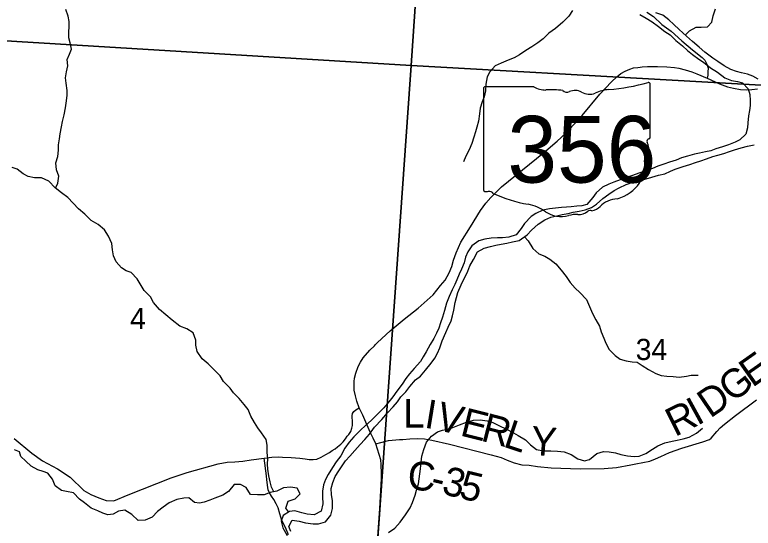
# Model space of a CAD drawing. Extents: x -8.2 to 34, y 0 to 22.
# Drawn here: x 3.755 to 5.214, y 18.871 to 19.885 of the extents above; entities that cross this region are included whole.
import ezdxf

# ---------------------------------------------------------------- set-up
doc = ezdxf.new("R2010")
doc.units = 0
for name, color, linetype in [('GM_X_Corporation', 7, 'Continuous'), ('GM_X_County_Road', 7, 'Continuous'), ('GM_X_County_Road_Text', 7, 'Continuous'), ('GM_X_Major_River', 7, 'Continuous'), ('GM_X_Minor_River', 7, 'Continuous'), ('GM_X_Section_Text', 7, 'Continuous'), ('GM_X_State_Location', 7, 'Continuous'), ('GM_X_State_Route', 7, 'Continuous'), ('GM_X_State_Shield', 7, 'Continuous'), ('GM_X_Township_Road', 7, 'Continuous')]:
    doc.layers.add(name, color=color, linetype=linetype)

msp = doc.modelspace()

# ---------------------------------------------------------------- linework, layer by layer
at = {"layer": 'GM_X_Corporation'}
for points in [[(4.607, 20.8038), (4.5379, 19.7849), (3.5308, 19.8461), (3.6063, 20.8752)], [(5.6414, 20.7386), (5.5693, 19.7272), (4.5379, 19.7849), (4.607, 20.8038)], [(3.5308, 19.8461), (4.5379, 19.7849), (4.465, 18.749), (3.459, 18.8121), (3.474, 19.0276), (3.5026, 19.4408)], [(4.5379, 19.7849), (5.5693, 19.7272), (5.5363, 19.3151), (5.5032, 18.9017), (5.4857, 18.6849), (4.465, 18.749)]]:
    msp.add_lwpolyline(points, close=True, dxfattribs=at)
at = {"layer": 'GM_X_County_Road'}
msp.add_lwpolyline([(4.4679, 19.0374), (4.4779, 19.0404), (4.4929, 19.0441), (4.5151, 19.0461), (4.5212, 19.0462), (4.5351, 19.0475), (4.5503, 19.0479), (4.5639, 19.0473), (4.5787, 19.0448), (4.6137, 19.0366), (4.6961, 19.0158), (4.7154, 19.0105), (4.7277, 19.0054), (4.7413, 18.9998), (4.7567, 18.9961), (4.7707, 18.9952), (4.7878, 18.9927), (4.8147, 18.9898), (4.8716, 18.9879), (4.9192, 18.9886), (4.9437, 18.9905), (4.9718, 18.996), (4.9816, 18.998), (5.0094, 19.0035), (5.0206, 19.0079), (5.0312, 19.0126), (5.0486, 19.0207), (5.073, 19.0288), (5.1145, 19.0416), (5.1272, 19.0459), (5.1305, 19.0487), (5.1419, 19.0618), (5.1482, 19.0694), (5.1568, 19.0762), (5.1785, 19.0933), (5.2199, 19.1245)], dxfattribs=at)
at = {"layer": 'GM_X_Major_River'}
for points in [[(5.1435, 19.7929), (5.1337, 19.7998), (5.1181, 19.8116), (5.1071, 19.8211), (5.0935, 19.8325), (5.0817, 19.8428), (5.0673, 19.8561), (5.0567, 19.8659), (5.0472, 19.8754), (5.0351, 19.8846), (5.021, 19.8895)], [(4.9895, 19.8861), (5.0024, 19.8789), (5.0142, 19.8717), (5.0267, 19.8625), (5.0388, 19.8523), (5.0495, 19.8454), (5.0608, 19.8348), (5.0737, 19.8242), (5.084, 19.8146), (5.0938, 19.807), (5.1064, 19.7975), (5.1158, 19.7915), (5.1295, 19.7804), (5.1431, 19.7717), (5.1576, 19.761), (5.1705, 19.7557), (5.1826, 19.7538), (5.1925, 19.7507), (5.2035, 19.7393), (5.2072, 19.728), (5.208, 19.7162), (5.208, 19.7059), (5.2065, 19.6964), (5.2046, 19.6854), (5.2034, 19.6721), (5.2027, 19.6619), (5.1989, 19.6497), (5.1875, 19.6384), (5.178, 19.6338), (5.1651, 19.6285), (5.1529, 19.6243), (5.14, 19.6202), (5.1298, 19.6168), (5.1192, 19.6145), (5.1078, 19.6122), (5.0975, 19.6096), (5.0839, 19.6062), (5.0721, 19.6028), (5.0615, 19.5978), (5.0486, 19.5941), (5.0368, 19.5903), (5.0254, 19.5861), (5.0144, 19.5819), (5.0027, 19.5774), (4.9875, 19.5721), (4.975, 19.5675), (4.9624, 19.5638), (4.9507, 19.5592), (4.9381, 19.5547), (4.9287, 19.5509), (4.9158, 19.5444), (4.9036, 19.5338), (4.8968, 19.524), (4.885, 19.5107), (4.8751, 19.5076), (4.8649, 19.5069), (4.8543, 19.5058), (4.8448, 19.505), (4.8349, 19.5043), (4.8228, 19.5031), (4.811, 19.5016), (4.7977, 19.4994), (4.7845, 19.4929), (4.775, 19.4869)], [(5.2232, 19.7583), (5.213, 19.764), (5.2027, 19.7678), (5.1906, 19.7709), (5.1807, 19.7732), (5.1697, 19.7774), (5.1561, 19.7842), (5.1435, 19.7929)], [(4.4082, 19.0038), (4.4169, 19.0133), (4.4268, 19.0243), (4.4374, 19.0364), (4.4462, 19.0463), (4.4553, 19.0569), (4.4651, 19.0702), (4.48, 19.0858), (4.491, 19.0987), (4.502, 19.1108), (4.5111, 19.1207), (4.5175, 19.1305), (4.527, 19.1404), (4.5354, 19.151), (4.5464, 19.1639), (4.5563, 19.1715), (4.5661, 19.1829), (4.5771, 19.1969), (4.5847, 19.2068), (4.5897, 19.2167), (4.5942, 19.2269), (4.5992, 19.241), (4.6064, 19.2577), (4.6109, 19.2679), (4.617, 19.2808), (4.6197, 19.2907), (4.6223, 19.3017), (4.625, 19.3165), (4.6277, 19.3268), (4.6303, 19.3366), (4.6364, 19.3518), (4.6497, 19.3784), (4.6539, 19.389), (4.6607, 19.4019), (4.6687, 19.4167), (4.6824, 19.4243), (4.6949, 19.4277), (4.7051, 19.4303), (4.7157, 19.4322), (4.7271, 19.4341), (4.7381, 19.4364), (4.751, 19.439), (4.767, 19.4504), (4.7757, 19.4599), (4.789, 19.4717), (4.8019, 19.48), (4.814, 19.4853), (4.8258, 19.4883), (4.8361, 19.4906), (4.8478, 19.4929), (4.8581, 19.4951), (4.8698, 19.497), (4.8816, 19.5), (4.8945, 19.5046), (4.904, 19.511), (4.9169, 19.522), (4.9287, 19.5311), (4.9393, 19.5383), (4.9491, 19.5436), (4.9624, 19.5497), (4.9761, 19.5543), (4.9882, 19.5577), (5.0023, 19.5614), (5.0137, 19.5645), (5.0266, 19.5683), (5.0391, 19.5713), (5.0501, 19.5762), (5.0596, 19.58), (5.0751, 19.5857), (5.0884, 19.5895), (5.0994, 19.5933), (5.1104, 19.5967), (5.1214, 19.6004), (5.134, 19.605), (5.1438, 19.608), (5.1556, 19.6114), (5.167, 19.6152), (5.1768, 19.6186), (5.1897, 19.6224), (5.2023, 19.6258), (5.2159, 19.6285)], [(4.775, 19.4869), (4.7621, 19.4732), (4.7552, 19.4633), (4.745, 19.4508), (4.7309, 19.4459), (4.718, 19.4448), (4.7085, 19.4448), (4.6956, 19.444), (4.6835, 19.4418), (4.6714, 19.4384), (4.6577, 19.4285), (4.6497, 19.4167), (4.6455, 19.4061), (4.6425, 19.3955), (4.6372, 19.3826), (4.633, 19.3727), (4.6284, 19.3617), (4.6239, 19.3522), (4.6189, 19.3416), (4.6129, 19.3287), (4.6079, 19.3158), (4.6038, 19.3013), (4.5996, 19.2877), (4.5958, 19.2767), (4.5924, 19.266), (4.5882, 19.2562), (4.5825, 19.2459), (4.5753, 19.2338), (4.5677, 19.2193), (4.5616, 19.2095), (4.5563, 19.2), (4.5441, 19.1863), (4.5346, 19.1761), (4.5274, 19.1666), (4.5202, 19.1556), (4.5096, 19.1416), (4.5016, 19.1302), (4.494, 19.1207), (4.4838, 19.1089), (4.4709, 19.0953), (4.4587, 19.0839), (4.4477, 19.074), (4.4378, 19.0645), (4.4245, 19.0516), (4.4151, 19.0406), (4.4071, 19.0289), (4.3991, 19.0141), (4.3896, 19.0019), (4.3824, 18.9905), (4.3737, 18.9769), (4.3683, 18.967), (4.3645, 18.9568), (4.3626, 18.9442), (4.3626, 18.9325), (4.363, 18.9188), (4.36, 18.9047), (4.3463, 18.8972), (4.3323, 18.8983), (4.322, 18.901), (4.308, 18.9052), (4.2977, 18.9037), (4.2848, 18.8961), (4.2807, 18.8847), (4.2844, 18.8714), (4.2928, 18.8562)], [(4.3004, 18.8645), (4.2962, 18.8744), (4.303, 18.8866), (4.3163, 18.8846), (4.3288, 18.8812), (4.344, 18.8793), (4.355, 18.8793), (4.3683, 18.8835), (4.3789, 18.8967), (4.3824, 18.91), (4.3824, 18.9248), (4.3805, 18.9374), (4.3801, 18.9495), (4.3831, 18.9613), (4.3877, 18.9727), (4.3949, 18.9844), (4.4014, 18.9943), (4.4082, 19.0038)]]:
    msp.add_lwpolyline(points, dxfattribs=at)
at = {"layer": 'GM_X_Minor_River'}
for points in [[(3.8352, 19.5427), (3.8395, 19.5527), (3.8414, 19.5663), (3.8372, 19.5792), (3.836, 19.5925), (3.8394, 19.6054), (3.8409, 19.6176), (3.8413, 19.6282), (3.8428, 19.6403), (3.8443, 19.6502), (3.8466, 19.6642), (3.8488, 19.6745), (3.8522, 19.6877), (3.8545, 19.7014), (3.8567, 19.7154), (3.8579, 19.7264), (3.8578, 19.7359), (3.8563, 19.7503), (3.8548, 19.7606), (3.8567, 19.7727), (3.8593, 19.7845), (3.8578, 19.797), (3.8627, 19.8072), (3.8668, 19.8171), (3.8638, 19.83), (3.8615, 19.8399), (3.8615, 19.8516), (3.8619, 19.8615), (3.8619, 19.8721), (3.8599, 19.8827), (3.8554, 19.896)], [(4.8566, 19.8935), (4.8494, 19.8829), (4.8373, 19.8707), (4.8229, 19.8582), (4.81, 19.8487), (4.7987, 19.8381), (4.7881, 19.8297), (4.7764, 19.8218), (4.7646, 19.8146), (4.7518, 19.8062), (4.7416, 19.8001), (4.7298, 19.7959), (4.7158, 19.7895), (4.7037, 19.7842), (4.6931, 19.7724), (4.6878, 19.7625), (4.6852, 19.7481), (4.6848, 19.7352), (4.6818, 19.7231), (4.6784, 19.7136), (4.6743, 19.7011), (4.6732, 19.6897), (4.6709, 19.6749), (4.6679, 19.6635), (4.6649, 19.654), (4.6618, 19.6438), (4.6577, 19.6309), (4.6524, 19.6188), (4.646, 19.6059), (4.6415, 19.5949)], [(5.079, 19.8452), (5.0876, 19.8534), (5.1008, 19.861), (5.1107, 19.8606), (5.1232, 19.8614), (5.1319, 19.8709), (5.1345, 19.883), (5.1394, 19.8974)], [(4.2668, 18.9428), (4.2616, 18.9517), (4.2594, 18.9623), (4.2567, 18.9744), (4.2548, 18.9873), (4.254, 18.9976), (4.2548, 19.0086), (4.2536, 19.0207), (4.2532, 19.0347), (4.2513, 19.0461), (4.2418, 19.0594), (4.235, 19.0689), (4.2282, 19.0795), (4.2213, 19.0924), (4.216, 19.1053), (4.2081, 19.1151), (4.1982, 19.1269), (4.1865, 19.1383), (4.18, 19.1477), (4.1671, 19.161), (4.1607, 19.1716), (4.1489, 19.1838), (4.1364, 19.1955), (4.1247, 19.2054), (4.1152, 19.2198), (4.1121, 19.2323), (4.1125, 19.2425), (4.1068, 19.2566), (4.0943, 19.2645), (4.081, 19.2698), (4.0655, 19.2816), (4.0534, 19.2922), (4.0405, 19.3032), (4.0287, 19.3168), (4.023, 19.3278), (4.0105, 19.3407), (4.0045, 19.3506), (3.9965, 19.3635), (3.9844, 19.376), (3.9749, 19.3794), (3.9654, 19.3855), (3.9548, 19.3972), (3.9499, 19.409), (3.9476, 19.4211), (3.9464, 19.4336), (3.9396, 19.448), (3.9316, 19.4602), (3.9191, 19.4712), (3.9055, 19.4791), (3.8933, 19.4913), (3.8808, 19.5019), (3.8596, 19.5246), (3.8471, 19.5333), (3.8346, 19.5432), (3.8221, 19.5565), (3.8077, 19.5629), (3.7937, 19.5633), (3.7812, 19.5655), (3.7713, 19.5709), (3.7592, 19.58), (3.7493, 19.5834)], [(4.7619, 19.4468), (4.7692, 19.4386), (4.7783, 19.4238), (4.7901, 19.4129), (4.8022, 19.4083), (4.8117, 19.4022), (4.8234, 19.3935), (4.8344, 19.381), (4.8439, 19.3681), (4.8523, 19.356), (4.8617, 19.3454), (4.8712, 19.3363), (4.8841, 19.3226), (4.8902, 19.3086), (4.8959, 19.2949), (4.9027, 19.2828), (4.9099, 19.2699), (4.9133, 19.2589), (4.9187, 19.246), (4.9228, 19.2365), (4.9293, 19.224), (4.9407, 19.2123), (4.9509, 19.2051), (4.9626, 19.2013), (4.9747, 19.1998), (4.9846, 19.1986), (4.9944, 19.1926), (5.007, 19.1842), (5.021, 19.1766), (5.0316, 19.1725), (5.0429, 19.171), (5.0554, 19.1706), (5.0676, 19.1691), (5.0816, 19.1714), (5.0914, 19.1729), (5.105, 19.1729)], [(4.4931, 18.8623), (4.5056, 18.871), (4.5158, 18.8828), (4.5264, 18.8972), (4.5358, 18.9112), (4.5407, 18.9219), (4.546, 18.9359), (4.5487, 18.9461), (4.5524, 18.9583), (4.5536, 18.9681), (4.5547, 18.9784), (4.5566, 18.9879), (4.5577, 19.0012), (4.5592, 19.0129), (4.5626, 19.0262), (4.5683, 19.041), (4.5781, 19.0524), (4.5902, 19.0615), (4.6, 19.0645), (4.6103, 19.0664), (4.6205, 19.0695), (4.6333, 19.0748), (4.647, 19.0805), (4.661, 19.0843), (4.6742, 19.085), (4.6882, 19.0832), (4.6992, 19.0797), (4.7121, 19.0729), (4.7246, 19.0669), (4.7401, 19.0593), (4.7496, 19.054), (4.7636, 19.0453), (4.7735, 19.0358), (4.7852, 19.0263), (4.7996, 19.0237), (4.814, 19.0237), (4.8273, 19.0233), (4.8405, 19.0214), (4.8538, 19.0165), (4.8674, 19.0081), (4.8803, 19.0036), (4.8905, 19.0063), (4.9045, 19.0184), (4.9182, 19.0226), (4.9291, 19.0218), (4.9413, 19.0196), (4.9522, 19.0165), (4.9655, 19.0139), (4.9784, 19.0124), (4.9886, 19.0131), (5.0015, 19.0184), (5.0147, 19.0272), (5.0253, 19.0336), (5.0393, 19.0397), (5.0533, 19.0427), (5.0632, 19.045), (5.0756, 19.0473), (5.0874, 19.0507), (5.1014, 19.0587), (5.1135, 19.0682)], [(4.2963, 18.9028), (4.2905, 18.9107), (4.295, 18.924), (4.3086, 18.9289), (4.3188, 18.9388), (4.3124, 18.9502), (4.2991, 18.9521), (4.2855, 18.9506), (4.2723, 18.9441), (4.2594, 18.9411), (4.2476, 18.9365), (4.234, 18.9365), (4.2204, 18.9376), (4.2117, 18.9513), (4.2007, 18.957), (4.1878, 18.9573), (4.1772, 18.9433), (4.1655, 18.9361), (4.15, 18.93), (4.1397, 18.9262), (4.1291, 18.9224), (4.1193, 18.9205), (4.1095, 18.9216), (4.0988, 18.9311), (4.0886, 18.9303), (4.0746, 18.9273), (4.0599, 18.9212), (4.0477, 18.9121), (4.0368, 18.9038), (4.0262, 18.8927), (4.0122, 18.8867), (3.9985, 18.8863), (3.986, 18.898), (3.972, 18.9067), (3.9595, 18.9045), (3.9493, 18.8988), (3.9387, 18.8972), (3.9285, 18.9003), (3.919, 18.9048), (3.9054, 18.9105), (3.8921, 18.9207), (3.8826, 18.9283), (3.8709, 18.9405), (3.8569, 18.9435), (3.847, 18.9454), (3.8341, 18.9545), (3.8292, 18.9677), (3.8201, 18.9795), (3.8106, 18.9829), (3.8004, 18.9863), (3.7871, 18.9935), (3.7765, 19.0034), (3.7667, 19.0125), (3.764, 19.0219), (3.7538, 19.0257)]]:
    msp.add_lwpolyline(points, dxfattribs=at)
at = {"layer": 'GM_X_State_Route'}
for points in [[(4.4716, 19.2377), (4.4966, 19.261), (4.5239, 19.2836), (4.5517, 19.3057), (4.5814, 19.3321), (4.5957, 19.3501), (4.6049, 19.3609), (4.6127, 19.3754), (4.6182, 19.388), (4.6218, 19.4007), (4.6266, 19.4147), (4.636, 19.4357), (4.6548, 19.4662), (4.6749, 19.4983), (4.6851, 19.5132), (4.6952, 19.5242), (4.7164, 19.5451), (4.7996, 19.6125), (4.8263, 19.6353), (4.8428, 19.6508), (4.8757, 19.6865), (4.9104, 19.7287), (4.9334, 19.7531), (4.944, 19.763), (4.9523, 19.7691), (4.961, 19.7742), (4.9701, 19.778), (4.9773, 19.7802), (4.9855, 19.7814), (4.9906, 19.782)], [(4.9906, 19.782), (4.9946, 19.7825), (5.0046, 19.7829), (5.0133, 19.7829), (5.0249, 19.7831), (5.0433, 19.7823), (5.0579, 19.7812), (5.067, 19.7799), (5.0795, 19.7768), (5.0927, 19.7727), (5.1022, 19.7685), (5.1225, 19.7598), (5.1469, 19.7486), (5.1632, 19.7427), (5.175, 19.7401), (5.1884, 19.7376), (5.2006, 19.737), (5.2112, 19.7374), (5.222, 19.7391)], [(4.4792, 18.9786), (4.4787, 18.997), (4.4776, 19.0061), (4.4679, 19.0374), (4.4625, 19.0488), (4.4568, 19.0605), (4.4422, 19.0941), (4.4352, 19.1088), (4.4308, 19.1219), (4.4278, 19.1325), (4.4255, 19.1435), (4.4251, 19.1515), (4.4251, 19.1604), (4.4259, 19.1672), (4.4282, 19.1774), (4.4331, 19.1901), (4.438, 19.1992), (4.4428, 19.2072), (4.456, 19.2229), (4.4654, 19.2315), (4.4673, 19.2337), (4.4716, 19.2377)], [(4.4701, 18.827), (4.4757, 18.909), (4.4791, 18.9687), (4.4793, 18.9745), (4.4792, 18.9786)]]:
    msp.add_lwpolyline(points, dxfattribs=at)
at = {"layer": 'GM_X_State_Shield'}
for p, q in [((4.7804, 19.7431), (4.6838, 19.7431)), ((5.0102, 19.6434), (5.0102, 19.7481)), ((4.6806, 19.7397), (4.6806, 19.5395)), ((5.0102, 19.6434), (5.0102, 19.6434))]:
    msp.add_line(p, q, dxfattribs=at)
for centre, major_axis, start_param, end_param in [((4.6844, 19.7401), (0.00382, 0), 1.712693, 3.28349), ((4.8034, 19.7663), (0.037, 0), 4.042523, 4.731795), ((4.8928, 20.0159), (0.3495, 0), 4.814394, 5.042369), ((5.0065, 19.7485), (0.00367, 0), 6.141152, 7.989035), ((4.8156, 19.6308), (0.133, 0), 1.404758, 1.657858), ((4.8458, 19.7411), (0.0107, 0), 3.836095, 5.185415), ((4.8615, 19.718), (0.0222, 0), 0.950623, 2.079405), ((4.8902, 19.7497), (0.0267, 0), 4.081561, 5.145723), ((4.9374, 19.682), (0.0703, 0), 1.699011, 2.107814), ((5.0063, 19.643), (0.00393, 0), 5.05454, 6.418171), ((5.0093, 19.6357), (0.00568, 0), 1.883978, 3.671073), ((4.9732, 19.6225), (0.0341, 0), 5.934695, 6.695948), ((5.0233, 19.5996), (0.0248, 0), 2.387724, 3.262537), ((4.9124, 19.5863), (0.0874, 0), 5.101752, 6.440018), ((4.6844, 19.5391), (0.00385, 0), 3.00124, 4.508301), ((4.685, 19.5596), (0.0294, 0), 4.665946, 4.897461), ((4.691, 19.528), (0.0106, 0), 0.519207, 1.627899), ((4.8248, 19.7078), (0.2524, 0), 4.195997, 4.488961), ((4.7496, 19.4496), (0.079, 0), 0.823519, 1.323587), ((4.9492, 19.4834), (0.0479, 0), 1.647645, 2.488434), ((4.835, 19.527), (0.0501, 0), 4.026481, 4.996735), ((4.8676, 19.512), (0.0267, 0), 4.691044, 5.507374), ((4.8918, 19.4926), (0.00752, 0), 1.147584, 2.315152), ((4.8886, 19.5201), (0.0282, 0), 4.937069, 5.64225), ((4.864, 19.4578), (0.0412, 0), 1.495662, 1.94098)]:
    msp.add_ellipse(centre, major_axis=major_axis, ratio=0.8, start_param=start_param, end_param=end_param, dxfattribs=at)
at = {"layer": 'GM_X_Township_Road'}
for points in [[(5.0038, 19.8908), (5.0168, 19.8817), (5.0329, 19.8663), (5.0516, 19.8527), (5.0726, 19.8336), (5.0936, 19.8163), (5.113, 19.8011), (5.1181, 19.7954), (5.1223, 19.7876), (5.1248, 19.7797), (5.1243, 19.7726), (5.1238, 19.7658), (5.1225, 19.7598)], [(3.7537, 19.048), (3.7886, 19.0189), (3.8094, 19.004), (3.8389, 18.9882), (3.8639, 18.9714), (3.8911, 18.9454), (3.9047, 18.9372), (3.9209, 18.9306), (3.9351, 18.9258), (3.9503, 18.9252), (3.9788, 18.9369), (4.0633, 18.9704), (4.0953, 18.9812), (4.1567, 18.9983), (4.1744, 19.0015), (4.1893, 19.0021), (4.2054, 19.0034), (4.2219, 19.0056), (4.2472, 19.0095), (4.2625, 19.0114), (4.2758, 19.0116), (4.2836, 19.0112), (4.3006, 19.0105), (4.3177, 19.0095), (4.3285, 19.0078), (4.3366, 19.0063), (4.3442, 19.0063), (4.3514, 19.0075), (4.3601, 19.0114), (4.3692, 19.0164), (4.3764, 19.0205), (4.3819, 19.0241), (4.3874, 19.0275), (4.3922, 19.0315), (4.3986, 19.037), (4.4033, 19.0414), (4.4079, 19.0471), (4.4115, 19.0526), (4.4149, 19.0558), (4.4185, 19.0619), (4.4208, 19.0687), (4.4217, 19.0736), (4.4219, 19.0778), (4.4221, 19.0836), (4.4213, 19.0886), (4.4215, 19.0929), (4.4221, 19.0973), (4.4246, 19.1013), (4.4287, 19.1047), (4.4352, 19.1088)], [(4.2955, 18.8576), (4.2896, 18.8723), (4.2821, 18.8858), (4.2781, 18.8991), (4.2749, 18.9108), (4.2711, 18.9188), (4.2667, 18.9275), (4.262, 18.9339), (4.2574, 18.9417), (4.2555, 18.9466), (4.2546, 18.951), (4.2529, 18.9665), (4.2519, 18.9745), (4.2472, 19.0095)]]:
    msp.add_lwpolyline(points, dxfattribs=at)

# ---------------------------------------------------------------- texts
at = {"layer": 'GM_X_County_Road_Text'}
for s, rotation, p in [('E', 35.1296, (5.212, 19.1477)), ('G', 37.9142, (5.1731, 19.1174)), ('D', 34.2098, (5.1285, 19.0869)), ('L', 0.0386, (4.522, 19.0696)), ('I', 350.7173, (4.5621, 19.0698)), ('V', 346.2288, (4.584, 19.0663)), ('R', 26.4987, (5.0591, 19.0506)), ('I', 28.7429, (5.103, 19.0726)), ('E', 345.9534, (4.6325, 19.0544)), ('R', 345.3977, (4.6736, 19.0441)), ('L', 341.6274, (4.7178, 19.0326)), ('Y', 355.3769, (4.7724, 19.0163)), ('C', 355.8749, (4.5294, 18.9475)), ('3', 346.4863, (4.5962, 18.9391)), ('5', 346.4686, (4.6302, 18.9309)), ('-', 346.5695, (4.5735, 18.9445))]:
    msp.add_text(s, height=0.0568, rotation=rotation, dxfattribs=at).set_placement(p)
at = {"layer": 'GM_X_Section_Text'}
for s, height, p in [('4', 0.0419, (3.9823, 19.2643)), ('34', 0.04186, (4.9815, 19.2031))]:
    msp.add_text(s, height=height, rotation=0, dxfattribs=at).set_placement(p)
at = {"layer": 'GM_X_State_Location'}
for s in ['s', 'r']:
    msp.add_text(s, height=0.000189, dxfattribs=at).set_placement((4.8417, 19.6263))
msp.add_text('356', height=0.000189, rotation=0, dxfattribs=at).set_placement((4.7748, 19.6125))
at = {"layer": 'GM_X_State_Shield'}
msp.add_text('356', height=0.13184, dxfattribs=at).set_placement((4.728, 19.5537))

doc.saveas('drawing.dxf')
